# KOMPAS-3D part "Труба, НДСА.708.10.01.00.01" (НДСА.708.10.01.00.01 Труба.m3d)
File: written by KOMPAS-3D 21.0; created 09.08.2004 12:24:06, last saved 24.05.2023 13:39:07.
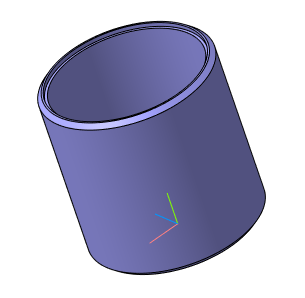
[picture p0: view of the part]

Document properties: Полное имя файла: C:\Users\s.pischagina\Desktop\PLM\НДСА.708.10.01.00.01 Труба.m3d; Автор: Устинов А.В.; Организация: Эсто-вакуум

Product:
- Part/product: Труба  | designation НДСА.708.10.01.00.01
    Материал: Труба$d180х10 ГОСТ 8732-78;20 ГОСТ 8731-74$ (density 7859 kg/m3)
    Масса: 7.337365
    Форматы листов документа: A4
    additional columns: <item xmlns="http://appius.ru/pdm" xmlns:xs="http://www.w3.org/2001/XMLSchema" x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; <item xmlns="http://appius.ru/pdm" xmlns:xs="http://www.w3.org/2001/XMLSchema" x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; <item xmlns="http://appius.ru/pdm" xmlns:xs="http://www.w3.org/2001/XMLSchema" x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

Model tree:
1. Плоскость XY
2. Плоскость ZX
3. Плоскость ZY
4. Начало координат
5. Эскиз:1
6. Операция выдавливания:1
     Расстояние 1 = 180
7. Эскиз:2  (labels: Операция выдавливания:1; Операция выдавливания:1)
8. Вырезать элемент выдавливания:1
     Расстояние 2 = 4.5
9. Эскиз:15  (labels: Операция выдавливания:1; Операция выдавливания:1)
10. Вырезать элемент выдавливания:15
     Расстояние 2 = 4.5
11. Фаска:2  (labels: Операция выдавливания:1; Операция выдавливания:1)
     Угол = 45; Длина 1 = 5; Длина 2 = 5
12. Эскиз:14
13. Вырезать элемент выдавливания:14  (labels: Труба$d180х10 ГОСТ 8732-78;20 ГОСТ 8731-74$)
     Расстояние 1 = 90

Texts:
  НДСА.708.10.01.00.01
